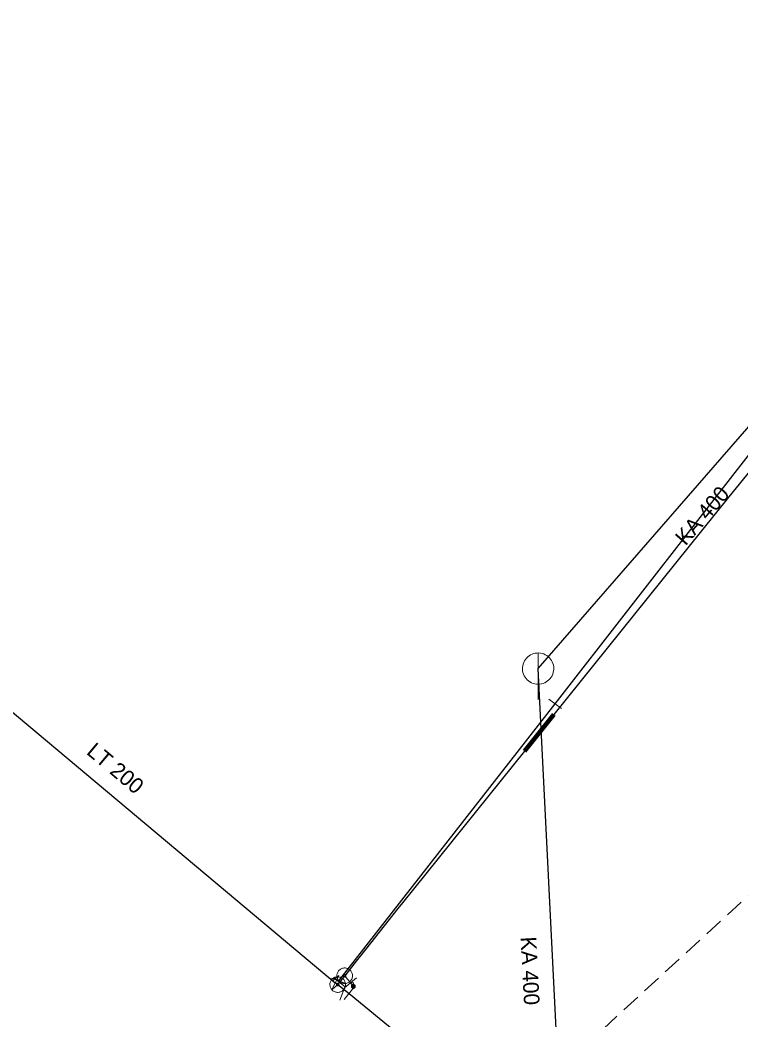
# Model space of a CAD drawing. Extents: x -790267 to -789874, y -989766 to -989454.
# Drawn here: x -790050.4 to -790004.3, y -989730.1 to -989666 of the extents above; entities that cross this region are included whole.
import ezdxf

# ---------------------------------------------------------------- set-up
doc = ezdxf.new("R2010")
doc.units = 0
doc.header["$LTSCALE"] = 0.4
doc.linetypes.add('MEDIUM_DASHED', pattern=[4.5, 3, -1.5])
doc.layers.add('1', color=7, linetype='Continuous')
for name, color, linetype, lineweight in [('14', 7, 'Continuous', 13), ('17', 7, 'Continuous', 25), ('22', 7, 'Continuous', 13), ('3', 7, 'Continuous', 106), ('34', 7, 'Continuous', 13), ('47', 7, 'Continuous', 13), ('63', 7, 'MEDIUM_DASHED', 25), ('9', 7, 'Continuous', 13)]:
    doc.layers.add(name, color=color, linetype=linetype, lineweight=lineweight)

msp = doc.modelspace()

# ---------------------------------------------------------------- linework, layer by layer
at = {"layer": '14'}
for p, q in [((-790029.656, -989727.219), (-790029.289, -989727.67)), ((-790029.991, -989727.642), (-790030.103, -989727.785)), ((-790029.289, -989727.67), (-790029.103, -989727.901))]:
    msp.add_line(p, q, dxfattribs=at)
at = {"layer": '14', "lineweight": 25}
msp.add_lwpolyline([(-790015.27, -989747.72), (-790017.28, -989707.56), (-789997.47, -989684.8), (-789979.42, -989661.98), (-789971.89, -989652.27)], dxfattribs=at)
at = {"layer": '17'}
for p, q in [((-790030.022, -989727.55), (-790016.192, -989709.824)), ((-790030.103, -989727.785), (-790030.258, -989727.664)), ((-790030.103, -989727.785), (-790029.379, -989728.359)), ((-790029.379, -989728.359), (-790008.099, -989745.732))]:
    msp.add_line(p, q, dxfattribs=at)
for points in [[(-789973.42, -989657.67), (-789975.664, -989660.431), (-789977.556, -989662.759), (-789987.276, -989674.721), (-789997.491, -989687.245), (-790005.072, -989696.559), (-790016.278, -989710.509), (-790018.158, -989712.846), (-790025.949, -989722.546), (-790026.25, -989722.92), (-790028.329, -989725.546), (-790029.004, -989726.397), (-790029.656, -989727.219)], [(-790016.192, -989709.824), (-789997.342, -989685.576), (-789984.21, -989668.683)], [(-790062.846, -989700.676), (-790058.885, -989703.664), (-790030.258, -989727.664)], [(-790029.656, -989727.219), (-790029.829, -989727.44), (-790029.991, -989727.642)]]:
    msp.add_lwpolyline(points, dxfattribs=at)
at = {"layer": '22'}
msp.add_line((-790017.28, -989709.56), (-790017.279, -989706.56), dxfattribs=at)
msp.add_lwpolyline([(-790016.28, -989707.56), (-790016.285, -989707.451), (-790016.303, -989707.343), (-790016.333, -989707.237), (-790016.373, -989707.136), (-790016.425, -989707.039), (-790016.487, -989706.949), (-790016.559, -989706.866), (-790016.639, -989706.792), (-790016.727, -989706.726), (-790016.821, -989706.671), (-790016.921, -989706.626), (-790017.026, -989706.593), (-790017.133, -989706.571), (-790017.242, -989706.561), (-790017.352, -989706.563), (-790017.46, -989706.577), (-790017.567, -989706.602), (-790017.67, -989706.639), (-790017.768, -989706.688), (-790017.86, -989706.746), (-790017.946, -989706.815), (-790018.023, -989706.892), (-790018.092, -989706.978), (-790018.151, -989707.07), (-790018.199, -989707.168), (-790018.236, -989707.271), (-790018.262, -989707.378), (-790018.276, -989707.486), (-790018.279, -989707.596), (-790018.269, -989707.705), (-790018.248, -989707.812), (-790018.214, -989707.916), (-790018.17, -989708.016), (-790018.115, -989708.111), (-790018.049, -989708.199), (-790017.975, -989708.279), (-790017.892, -989708.351), (-790017.802, -989708.413), (-790017.706, -989708.465), (-790017.604, -989708.506), (-790017.499, -989708.536), (-790017.391, -989708.554), (-790017.281, -989708.56), (-790017.172, -989708.554), (-790017.064, -989708.536), (-790016.959, -989708.507), (-790016.857, -989708.466), (-790016.76, -989708.414), (-790016.67, -989708.352), (-790016.587, -989708.281), (-790016.512, -989708.201), (-790016.447, -989708.113), (-790016.391, -989708.019), (-790016.347, -989707.919), (-790016.313, -989707.815), (-790016.291, -989707.707), (-790016.281, -989707.598)], close=True, dxfattribs=at)
at = {"layer": '3'}
msp.add_line((-790016.278, -989710.509), (-790018.158, -989712.846), dxfattribs=at)
at = {"layer": '3', "lineweight": 100}
msp.add_line((-790016.278, -989710.509), (-790018.158, -989712.846), dxfattribs=at)
at = {"layer": '34'}
for p, q in [((-790016.592, -989709.525), (-790015.791, -989710.123)), ((-790030.49, -989727.374), (-790029.554, -989727.726)), ((-790029.598, -989727.952), (-790030.382, -989727.33)), ((-790028.9, -989727.355), (-790029.677, -989727.984)), ((-790029.966, -989728.774), (-790029.614, -989727.838)), ((-790029.068, -989727.966), (-790029.69, -989728.75))]:
    msp.add_line(p, q, dxfattribs=at)
at = {"layer": '47'}
msp.add_line((-790030.489, -989728.117), (-790030.099, -989727.788), dxfattribs=at)
for points in [[(-790029.966, -989727.611), (-790029.923, -989727.641), (-790029.877, -989727.667), (-790029.829, -989727.687), (-790029.78, -989727.703), (-790029.728, -989727.713), (-790029.676, -989727.718), (-790029.624, -989727.717), (-790029.572, -989727.711), (-790029.521, -989727.7), (-790029.471, -989727.683), (-790029.423, -989727.661), (-790029.378, -989727.634), (-790029.336, -989727.603), (-790029.298, -989727.568), (-790029.263, -989727.529), (-790029.233, -989727.486), (-790029.207, -989727.44), (-790029.187, -989727.392), (-790029.171, -989727.343), (-790029.161, -989727.291), (-790029.156, -989727.239), (-790029.157, -989727.186), (-790029.163, -989727.134), (-790029.174, -989727.083), (-790029.191, -989727.034), (-790029.213, -989726.986), (-790029.239, -989726.941), (-790029.271, -989726.899), (-790029.306, -989726.861), (-790029.345, -989726.826), (-790029.388, -989726.796), (-790029.434, -989726.77), (-790029.482, -989726.749), (-790029.531, -989726.734), (-790029.583, -989726.724), (-790029.635, -989726.718), (-790029.687, -989726.719), (-790029.739, -989726.725), (-790029.791, -989726.737), (-790029.84, -989726.754), (-790029.888, -989726.776), (-790029.933, -989726.802), (-790029.975, -989726.834), (-790030.013, -989726.869), (-790030.048, -989726.908), (-790030.078, -989726.951), (-790030.104, -989726.997), (-790030.124, -989727.044), (-790030.14, -989727.094), (-790030.15, -989727.146), (-790030.156, -989727.198), (-790030.154, -989727.25), (-790030.148, -989727.302), (-790030.137, -989727.353), (-790030.12, -989727.403), (-790030.098, -989727.451), (-790030.072, -989727.495), (-790030.04, -989727.538), (-790030.005, -989727.576)], [(-790030.496, -989727.476), (-790030.525, -989727.518), (-790030.551, -989727.564), (-790030.571, -989727.612), (-790030.587, -989727.662), (-790030.597, -989727.714), (-790030.602, -989727.766), (-790030.601, -989727.818), (-790030.594, -989727.87), (-790030.583, -989727.921), (-790030.567, -989727.971), (-790030.544, -989728.018), (-790030.517, -989728.063), (-790030.486, -989728.105), (-790030.45, -989728.143), (-790030.411, -989728.178), (-790030.369, -989728.207), (-790030.323, -989728.233), (-790030.274, -989728.254), (-790030.225, -989728.269), (-790030.173, -989728.279), (-790030.121, -989728.284), (-790030.068, -989728.283), (-790030.016, -989728.277), (-790029.966, -989728.266), (-790029.916, -989728.249), (-790029.869, -989728.226), (-790029.823, -989728.2), (-790029.782, -989728.168), (-790029.744, -989728.132), (-790029.709, -989728.093), (-790029.68, -989728.051), (-790029.654, -989728.005), (-790029.632, -989727.957), (-790029.618, -989727.907), (-790029.608, -989727.855), (-790029.602, -989727.804), (-790029.603, -989727.751), (-790029.609, -989727.699), (-790029.621, -989727.648), (-790029.638, -989727.598), (-790029.661, -989727.551), (-790029.687, -989727.506), (-790029.719, -989727.464), (-790029.755, -989727.426), (-790029.794, -989727.391), (-790029.836, -989727.362), (-790029.882, -989727.336), (-790029.93, -989727.315), (-790029.98, -989727.3), (-790030.032, -989727.29), (-790030.083, -989727.284), (-790030.135, -989727.286), (-790030.187, -989727.292), (-790030.239, -989727.304), (-790030.289, -989727.32), (-790030.336, -989727.343), (-790030.38, -989727.369), (-790030.423, -989727.401), (-790030.461, -989727.437)], [(-790029.706, -989727.283), (-790029.699, -989727.288), (-790029.692, -989727.292), (-790029.684, -989727.295), (-790029.676, -989727.298), (-790029.667, -989727.3), (-790029.659, -989727.3), (-790029.65, -989727.3), (-790029.642, -989727.299), (-790029.634, -989727.297), (-790029.625, -989727.295), (-790029.617, -989727.291), (-790029.61, -989727.286), (-790029.603, -989727.281), (-790029.597, -989727.276), (-790029.591, -989727.269), (-790029.586, -989727.262), (-790029.582, -989727.255), (-790029.579, -989727.247), (-790029.576, -989727.239), (-790029.574, -989727.23), (-790029.574, -989727.222), (-790029.574, -989727.213), (-790029.575, -989727.205), (-790029.576, -989727.196), (-790029.579, -989727.188), (-790029.583, -989727.18), (-790029.588, -989727.173), (-790029.593, -989727.166), (-790029.598, -989727.16), (-790029.605, -989727.154), (-790029.612, -989727.149), (-790029.619, -989727.145), (-790029.627, -989727.142), (-790029.635, -989727.139), (-790029.644, -989727.137), (-790029.652, -989727.136), (-790029.661, -989727.137), (-790029.669, -989727.138), (-790029.678, -989727.139), (-790029.686, -989727.142), (-790029.694, -989727.146), (-790029.701, -989727.151), (-790029.708, -989727.156), (-790029.714, -989727.161), (-790029.72, -989727.168), (-790029.725, -989727.175), (-790029.729, -989727.182), (-790029.732, -989727.19), (-790029.735, -989727.198), (-790029.737, -989727.207), (-790029.738, -989727.215), (-790029.737, -989727.224), (-790029.736, -989727.232), (-790029.734, -989727.24), (-790029.732, -989727.249), (-790029.728, -989727.257), (-790029.723, -989727.264), (-790029.718, -989727.271), (-790029.713, -989727.277)], [(-790030.167, -989727.734), (-790030.173, -989727.741), (-790030.176, -989727.748), (-790030.179, -989727.756), (-790030.182, -989727.764), (-790030.184, -989727.773), (-790030.184, -989727.781), (-790030.184, -989727.79), (-790030.183, -989727.798), (-790030.181, -989727.807), (-790030.179, -989727.815), (-790030.175, -989727.823), (-790030.17, -989727.83), (-790030.165, -989727.837), (-790030.16, -989727.843), (-790030.153, -989727.849), (-790030.146, -989727.855), (-790030.139, -989727.858), (-790030.131, -989727.861), (-790030.123, -989727.864), (-790030.114, -989727.866), (-790030.106, -989727.866), (-790030.097, -989727.866), (-790030.089, -989727.865), (-790030.079, -989727.864), (-790030.072, -989727.861), (-790030.064, -989727.857), (-790030.057, -989727.852), (-790030.05, -989727.847), (-790030.044, -989727.842), (-790030.038, -989727.835), (-790030.032, -989727.828), (-790030.029, -989727.821), (-790030.026, -989727.813), (-790030.023, -989727.805), (-790030.021, -989727.796), (-790030.02, -989727.788), (-790030.021, -989727.779), (-790030.022, -989727.771), (-790030.023, -989727.761), (-790030.026, -989727.754), (-790030.03, -989727.746), (-790030.035, -989727.739), (-790030.04, -989727.732), (-790030.045, -989727.726), (-790030.052, -989727.72), (-790030.059, -989727.714), (-790030.066, -989727.711), (-790030.074, -989727.708), (-790030.082, -989727.705), (-790030.091, -989727.703), (-790030.099, -989727.702), (-790030.108, -989727.703), (-790030.116, -989727.704), (-790030.125, -989727.706), (-790030.133, -989727.708), (-790030.141, -989727.712), (-790030.148, -989727.717), (-790030.155, -989727.722), (-790030.161, -989727.727)]]:
    msp.add_lwpolyline(points, close=True, dxfattribs=at)
msp.add_lwpolyline([(-790030.489, -989728.117), (-790030.026, -989727.21), (-790030.416, -989727.539)], dxfattribs=at)
at = {"layer": '63'}
msp.add_lwpolyline([(-790188.469, -989455.136), (-790139.344, -989496.446), (-790139.344, -989496.446), (-790029.929, -989518.217), (-790029.929, -989518.217), (-789963.498, -989555.061), (-789963.498, -989555.061), (-789946.75, -989559.527), (-789946.75, -989559.527), (-789908.79, -989634.89), (-789908.79, -989634.89), (-790051.142, -989765.519), (-790051.142, -989765.519), (-790157.208, -989714.719), (-790157.208, -989714.719), (-790153.3, -989672.851), (-790153.3, -989672.851), (-790266.065, -989576.274), (-790266.065, -989576.274), (-790235.362, -989502.586), (-790235.362, -989502.586), (-790189.028, -989455.694), (-790189.028, -989455.694)], close=True, dxfattribs=at)
at = {"layer": '9'}
for points in [[(-790029.229, -989727.695), (-790029.276, -989727.68), (-790029.233, -989727.664)], [(-790029.103, -989727.774), (-790029.103, -989727.681), (-790029.276, -989727.68)]]:
    msp.add_lwpolyline(points, dxfattribs=at)
for points in [[(-790029.23, -989727.9), (-790029.229, -989727.913), (-790029.227, -989727.926), (-790029.224, -989727.939), (-790029.219, -989727.951), (-790029.213, -989727.963), (-790029.206, -989727.974), (-790029.198, -989727.984), (-790029.188, -989727.994), (-790029.178, -989728.002), (-790029.167, -989728.009), (-790029.155, -989728.015), (-790029.143, -989728.02), (-790029.13, -989728.023), (-790029.117, -989728.025), (-790029.104, -989728.027), (-790029.091, -989728.027), (-790029.078, -989728.025), (-790029.065, -989728.022), (-790029.053, -989728.017), (-790029.041, -989728.011), (-790029.03, -989728.004), (-790029.02, -989727.996), (-790029.01, -989727.986), (-790029.002, -989727.976), (-790028.995, -989727.965), (-790028.989, -989727.953), (-790028.984, -989727.941), (-790028.981, -989727.928), (-790028.979, -989727.915), (-790028.977, -989727.902), (-790028.978, -989727.889), (-790028.98, -989727.876), (-790028.983, -989727.863), (-790028.988, -989727.851), (-790028.994, -989727.839), (-790029.001, -989727.828), (-790029.009, -989727.818), (-790029.019, -989727.808), (-790029.029, -989727.8), (-790029.04, -989727.793), (-790029.052, -989727.787), (-790029.064, -989727.782), (-790029.077, -989727.779), (-790029.09, -989727.777), (-790029.103, -989727.774), (-790029.116, -989727.775), (-790029.129, -989727.777), (-790029.142, -989727.78), (-790029.154, -989727.785), (-790029.166, -989727.791), (-790029.177, -989727.798), (-790029.187, -989727.806), (-790029.197, -989727.816), (-790029.205, -989727.826), (-790029.212, -989727.837), (-790029.218, -989727.849), (-790029.223, -989727.861), (-790029.226, -989727.874), (-790029.228, -989727.887)], [(-790029.21, -989727.9), (-790029.21, -989727.911), (-790029.208, -989727.922), (-790029.205, -989727.933), (-790029.201, -989727.943), (-790029.196, -989727.953), (-790029.19, -989727.962), (-790029.183, -989727.971), (-790029.175, -989727.979), (-790029.166, -989727.986), (-790029.157, -989727.992), (-790029.147, -989727.997), (-790029.137, -989728.001), (-790029.126, -989728.004), (-790029.115, -989728.006), (-790029.104, -989728.007), (-790029.093, -989728.008), (-790029.082, -989728.006), (-790029.071, -989728.003), (-790029.061, -989727.999), (-790029.051, -989727.994), (-790029.042, -989727.988), (-790029.033, -989727.981), (-790029.025, -989727.973), (-790029.018, -989727.964), (-790029.012, -989727.955), (-790029.007, -989727.945), (-790029.003, -989727.935), (-790029, -989727.924), (-790028.998, -989727.913), (-790028.997, -989727.902), (-790028.997, -989727.891), (-790028.999, -989727.88), (-790029.002, -989727.869), (-790029.006, -989727.859), (-790029.011, -989727.849), (-790029.017, -989727.84), (-790029.024, -989727.831), (-790029.032, -989727.823), (-790029.041, -989727.816), (-790029.05, -989727.81), (-790029.06, -989727.805), (-790029.07, -989727.801), (-790029.081, -989727.798), (-790029.092, -989727.796), (-790029.103, -989727.794), (-790029.114, -989727.794), (-790029.125, -989727.796), (-790029.136, -989727.799), (-790029.146, -989727.803), (-790029.156, -989727.808), (-790029.165, -989727.814), (-790029.174, -989727.821), (-790029.182, -989727.829), (-790029.189, -989727.838), (-790029.195, -989727.847), (-790029.2, -989727.857), (-790029.204, -989727.867), (-790029.207, -989727.878), (-790029.209, -989727.889)], [(-790029.191, -989727.9), (-790029.19, -989727.909), (-790029.189, -989727.918), (-790029.186, -989727.927), (-790029.183, -989727.935), (-790029.179, -989727.943), (-790029.174, -989727.951), (-790029.168, -989727.958), (-790029.162, -989727.964), (-790029.155, -989727.97), (-790029.147, -989727.975), (-790029.139, -989727.979), (-790029.131, -989727.982), (-790029.122, -989727.985), (-790029.113, -989727.986), (-790029.104, -989727.989), (-790029.095, -989727.988), (-790029.086, -989727.987), (-790029.077, -989727.984), (-790029.069, -989727.981), (-790029.061, -989727.977), (-790029.053, -989727.972), (-790029.046, -989727.966), (-790029.04, -989727.96), (-790029.034, -989727.953), (-790029.029, -989727.945), (-790029.025, -989727.937), (-790029.022, -989727.929), (-790029.019, -989727.92), (-790029.018, -989727.911), (-790029.016, -989727.902), (-790029.017, -989727.893), (-790029.018, -989727.884), (-790029.021, -989727.875), (-790029.024, -989727.867), (-790029.028, -989727.859), (-790029.033, -989727.851), (-790029.039, -989727.844), (-790029.045, -989727.838), (-790029.052, -989727.832), (-790029.06, -989727.827), (-790029.068, -989727.823), (-790029.076, -989727.82), (-790029.085, -989727.817), (-790029.094, -989727.816), (-790029.103, -989727.813), (-790029.112, -989727.814), (-790029.121, -989727.815), (-790029.13, -989727.818), (-790029.138, -989727.821), (-790029.146, -989727.825), (-790029.154, -989727.83), (-790029.161, -989727.836), (-790029.167, -989727.842), (-790029.173, -989727.849), (-790029.178, -989727.857), (-790029.182, -989727.865), (-790029.185, -989727.873), (-790029.188, -989727.882), (-790029.189, -989727.891)], [(-790029.171, -989727.9), (-790029.171, -989727.907), (-790029.169, -989727.914), (-790029.168, -989727.921), (-790029.165, -989727.927), (-790029.162, -989727.933), (-790029.158, -989727.939), (-790029.154, -989727.945), (-790029.149, -989727.95), (-790029.143, -989727.954), (-790029.137, -989727.958), (-790029.131, -989727.961), (-790029.125, -989727.964), (-790029.118, -989727.965), (-790029.111, -989727.967), (-790029.104, -989727.968), (-790029.097, -989727.969), (-790029.09, -989727.967), (-790029.083, -989727.966), (-790029.077, -989727.963), (-790029.07, -989727.96), (-790029.065, -989727.956), (-790029.059, -989727.952), (-790029.054, -989727.947), (-790029.05, -989727.941), (-790029.046, -989727.935), (-790029.043, -989727.929), (-790029.04, -989727.923), (-790029.038, -989727.916), (-790029.037, -989727.909), (-790029.036, -989727.902), (-790029.036, -989727.895), (-790029.037, -989727.888), (-790029.039, -989727.881), (-790029.042, -989727.875), (-790029.045, -989727.868), (-790029.049, -989727.863), (-790029.053, -989727.857), (-790029.058, -989727.852), (-790029.064, -989727.848), (-790029.069, -989727.844), (-790029.076, -989727.841), (-790029.082, -989727.838), (-790029.089, -989727.836), (-790029.096, -989727.835), (-790029.103, -989727.833), (-790029.11, -989727.833), (-790029.117, -989727.834), (-790029.124, -989727.836), (-790029.13, -989727.839), (-790029.136, -989727.842), (-790029.142, -989727.846), (-790029.148, -989727.85), (-790029.153, -989727.855), (-790029.157, -989727.861), (-790029.161, -989727.866), (-790029.164, -989727.873), (-790029.167, -989727.879), (-790029.168, -989727.886), (-790029.17, -989727.893)], [(-790029.151, -989727.9), (-790029.151, -989727.905), (-790029.15, -989727.91), (-790029.149, -989727.915), (-790029.147, -989727.919), (-790029.145, -989727.924), (-790029.142, -989727.928), (-790029.139, -989727.931), (-790029.135, -989727.935), (-790029.132, -989727.938), (-790029.128, -989727.941), (-790029.123, -989727.943), (-790029.119, -989727.945), (-790029.114, -989727.946), (-790029.109, -989727.947), (-790029.104, -989727.948), (-790029.099, -989727.949), (-790029.094, -989727.948), (-790029.089, -989727.947), (-790029.085, -989727.945), (-790029.08, -989727.943), (-790029.076, -989727.94), (-790029.072, -989727.937), (-790029.069, -989727.933), (-790029.066, -989727.93), (-790029.063, -989727.926), (-790029.061, -989727.921), (-790029.059, -989727.917), (-790029.058, -989727.912), (-790029.057, -989727.907), (-790029.056, -989727.902), (-790029.056, -989727.897), (-790029.057, -989727.892), (-790029.058, -989727.887), (-790029.06, -989727.883), (-790029.062, -989727.878), (-790029.065, -989727.874), (-790029.068, -989727.87), (-790029.071, -989727.867), (-790029.075, -989727.864), (-790029.079, -989727.861), (-790029.084, -989727.859), (-790029.088, -989727.857), (-790029.093, -989727.856), (-790029.098, -989727.855), (-790029.103, -989727.853), (-790029.108, -989727.853), (-790029.113, -989727.854), (-790029.118, -989727.855), (-790029.122, -989727.857), (-790029.127, -989727.859), (-790029.131, -989727.862), (-790029.134, -989727.865), (-790029.138, -989727.868), (-790029.141, -989727.872), (-790029.144, -989727.876), (-790029.146, -989727.881), (-790029.148, -989727.885), (-790029.149, -989727.89), (-790029.15, -989727.895)], [(-790029.131, -989727.9), (-790029.131, -989727.903), (-790029.131, -989727.906), (-790029.13, -989727.908), (-790029.129, -989727.911), (-790029.128, -989727.914), (-790029.126, -989727.916), (-790029.124, -989727.918), (-790029.122, -989727.92), (-790029.12, -989727.922), (-790029.118, -989727.924), (-790029.115, -989727.925), (-790029.112, -989727.926), (-790029.11, -989727.927), (-790029.107, -989727.927), (-790029.104, -989727.927), (-790029.101, -989727.929), (-790029.098, -989727.929), (-790029.095, -989727.928), (-790029.093, -989727.927), (-790029.09, -989727.926), (-790029.088, -989727.924), (-790029.085, -989727.922), (-790029.083, -989727.92), (-790029.082, -989727.918), (-790029.08, -989727.916), (-790029.079, -989727.913), (-790029.078, -989727.91), (-790029.077, -989727.908), (-790029.077, -989727.905), (-790029.075, -989727.902), (-790029.076, -989727.899), (-790029.076, -989727.896), (-790029.077, -989727.893), (-790029.078, -989727.891), (-790029.079, -989727.888), (-790029.081, -989727.886), (-790029.082, -989727.883), (-790029.084, -989727.881), (-790029.087, -989727.88), (-790029.089, -989727.878), (-790029.092, -989727.877), (-790029.094, -989727.876), (-790029.097, -989727.875), (-790029.1, -989727.875), (-790029.103, -989727.872), (-790029.106, -989727.873), (-790029.109, -989727.873), (-790029.111, -989727.874), (-790029.114, -989727.875), (-790029.117, -989727.876), (-790029.119, -989727.878), (-790029.121, -989727.879), (-790029.123, -989727.881), (-790029.125, -989727.884), (-790029.127, -989727.886), (-790029.128, -989727.889), (-790029.129, -989727.891), (-790029.13, -989727.894), (-790029.13, -989727.897)], [(-790029.112, -989727.9), (-790029.112, -989727.901), (-790029.112, -989727.902), (-790029.111, -989727.902), (-790029.111, -989727.903), (-790029.111, -989727.904), (-790029.11, -989727.905), (-790029.11, -989727.905), (-790029.109, -989727.906), (-790029.109, -989727.906), (-790029.108, -989727.907), (-790029.107, -989727.907), (-790029.106, -989727.907), (-790029.106, -989727.908), (-790029.105, -989727.908), (-790029.104, -989727.909), (-790029.103, -989727.909), (-790029.102, -989727.91), (-790029.102, -989727.909), (-790029.101, -989727.909), (-790029.1, -989727.909), (-790029.099, -989727.908), (-790029.099, -989727.908), (-790029.098, -989727.907), (-790029.098, -989727.907), (-790029.097, -989727.906), (-790029.097, -989727.905), (-790029.096, -989727.904), (-790029.096, -989727.904), (-790029.096, -989727.903), (-790029.095, -989727.902), (-790029.095, -989727.901), (-790029.095, -989727.9), (-790029.095, -989727.9), (-790029.096, -989727.899), (-790029.096, -989727.898), (-790029.097, -989727.897), (-790029.097, -989727.897), (-790029.098, -989727.896), (-790029.098, -989727.896), (-790029.099, -989727.895), (-790029.1, -989727.895), (-790029.101, -989727.894), (-790029.101, -989727.894), (-790029.102, -989727.894), (-790029.103, -989727.892), (-790029.104, -989727.892), (-790029.105, -989727.892), (-790029.105, -989727.892), (-790029.106, -989727.893), (-790029.107, -989727.893), (-790029.108, -989727.894), (-790029.108, -989727.894), (-790029.109, -989727.895), (-790029.109, -989727.895), (-790029.11, -989727.896), (-790029.11, -989727.897), (-790029.11, -989727.898), (-790029.111, -989727.898), (-790029.111, -989727.899)]]:
    msp.add_lwpolyline(points, close=True, dxfattribs=at)

# ---------------------------------------------------------------- texts
at = {"layer": '1'}
for s, rotation, p in [('KA 400', 49, (-790007.846, -989699.746)), ('LT 200', 320, (-790046.237, -989712.981)), ('KA 400', 273, (-790018.407, -989724.742))]:
    msp.add_text(s, height=1, rotation=rotation, dxfattribs=at).set_placement(p)

doc.saveas('drawing.dxf')
